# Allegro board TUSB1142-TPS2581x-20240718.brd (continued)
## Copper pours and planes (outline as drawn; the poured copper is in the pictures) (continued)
+3P3V_S5 on L4_VCC: 2.51,46.37 3.7,46.37 3.93,46.14 3.93,45.1 3.95,45 4.01,44.92 4.39,44.54 4.47,44.49 4.57,44.47 10.56,44.47 11.12,43.91 11.2,43.85 11.3,43.83 21.99,43.83 26.74,39.08 26.82,39.03 26.92,39.01 78.51,39.01 79.76,37.03 81.97,36.25 84.18,37.03 85.43,39.01 94.89,39.01 95.24,38.65 95.24,25.6 95.06,25.42 94.99,25.16 94.99,22.46 94.96,22.44 94.94,22.42 94.5,21.99 91.29,21.99 90.93,22.35 90.93,28.72 90.91,28.82 90.85,28.9 90.09,29.66 90.01,29.72 89.91,29.74 83.81,29.74 83.72,29.72 83.63,29.66 83.07,29.1 81.15,29.1 81.05,29.08 80.97,29.03 80.28,28.34 75.92,28.34 73.71,30.55 73.62,30.6 73.53,30.62 24.86,30.62 22.14,33.34 22.06,33.4 21.97,33.42 10.69,33.42 10.74,33.53 10.75,33.65 10.6,34.01 10.24,34.16 9.43,34.16 9.07,34.01 8.92,33.65 8.94,33.53 8.98,33.42 8.86,33.42 7.67,34.61 7.58,34.67 7.49,34.69 5.31,34.69 2.41,37.59 2.41,46.27 ; 10 cut-outs
+3P3V_U7401_S5 on TOP (solid shape): 32.79,26.2 32.79,24.12 32.68,24.02 31.62,24.02 31.38,24.11 31.13,24.02 30.86,24.02 30.68,24.02 30.47,24.02 29.97,24.53 29.97,26.18 30.09,26.31 32.68,26.31
+3P3V_U7401_S5 on BOTTOM (solid shape): outline of 303 points within 31.46,19.24 40.44,26.2
+3P3V_U7401_S5 on L3_IN1 (solid shape): outline of 404 points within 31.29,22.99 43.05,27.96
AUD_AGND on TOP (solid shape): 103.37,46.25 103.37,45.1 102.61,44.34 95.63,44.34 91.56,48.4 39.49,48.4 39.36,48.53 39.36,49.17 42.54,52.34 97.28,52.34
AUD_AGND on L2_GND1, L4_VCC, L5_GND2: outline of 102 points within 30.22,0.86 112.77,59.83
USBPWR_1_F on TOP (solid shape): outline of 82 points within 53.34,14.43 60.24,25.93
USBPWR_1_F on L4_VCC: 56.23,21.48 59.58,21.48 62.1,18.96 62.1,17.01 55.64,10.56 55.55,10.56 55.06,10.35 54.85,9.86 54.86,9.74 54.89,9.62 50.82,9.62 50.79,9.65 50.79,18.45 51.15,18.81 53.46,18.81 53.56,18.83 53.64,18.89 ; 1 cut-out
USBPWR_2_F on L4_VCC: 84.68,21.48 94.5,21.48 94.94,21.05 94.96,21.02 94.99,21.01 94.99,20.08 95.03,19.89 95.14,19.72 96.01,18.86 96.01,13.95 95.98,13.93 95.95,13.91 95.65,13.61 82.93,13.61 82.83,13.59 82.75,13.53 82.11,12.9 82.06,12.81 82.04,12.72 82.04,10.66 81.93,10.56 81.33,10.56 80.84,10.35 80.63,9.86 80.64,9.76 80.66,9.67 76.81,9.67 76.58,9.9 76.58,18.45 76.93,18.81 81.91,18.81 82.01,18.83 82.09,18.89 ; 1 cut-out

Small or netless copper shapes (teardrops, artwork), in the pictures only: 55 on TOP, 1 on L2_GND1, 1 on L4_VCC

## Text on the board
Ref Des/Silkscreen Bottom: 2025_RC_BK_FIO | REV:B00
Ref Des/Silkscreen Top: A37 | B1 | B37
L2_GND1: L2_GND1
L3_IN1: L3_IN1
L4_VCC: L4_VCC
L5_GND2: L5_GND2
DIMENSION: 75.0001 [2.953] | 149.4998 [5.886] | ∅3.0000 [∅0.118] | ∅1.0000 [∅0.039] | 132.0002 [5.197] | 177.5199 [6.989]
0.DXF-20240523-T: 65 | 148
User.8: 65 | 147
User.10: 65 | 147
User.13: 65 | 147
User.15: 75 | 147
User.21: 75 | 149.5
User.23: 75 | 149.5
User.26: 75.00 | 149.50
User.29: ******************************************* | * Drill Tolerance:                        * | * 1.PTH : +/-3MILS                        * | * 2.NPTH: +/-2MILS                        * | * 3.Oblong Slot PTH : +/-3MILS            * | * 4.Oblong Slot NPTH:Short Side:+/-2MILS  * | *                    Long  Side:+/-3MILS  * | *                                         * | * Mounting Hole Drill Tolerance:          * | * 1.PTH : +4/-0 MILS                      * | * 2.NPTH: +3/-0 MILS                      * | * Tooling Hole Drill Tolerance:           * | * 1.NPTH : +2/-0 MILS                     * | *                              2018/08/29 * | FIGURE | SIZE | 8.0 | 10.0 | 12.0 | 28.0 | 30.0 | 32.0 | 35.0 | 37.0 | 38.0 | 39.0 | 27.0 | 41.0 | 56.0 | 67.0 | 118.0 | 125.0 | 173.0 | 39.0x22.0 | 51.0x24.0 | 69.0x43.0 | 71.0x28.0 | 78.0x22.0 | 81.0x22.0 | 97.0x43.0 | 102.0x28.0 | DRILL CHART: TOP to BOTTOM | ALL UNITS ARE IN MILS | PLATED | NON-PLATED | QTY | 324 | 2482 | 60 | 18 | 4 | 2 | 24 | 13 | 1 | 72 | 6 | 7
